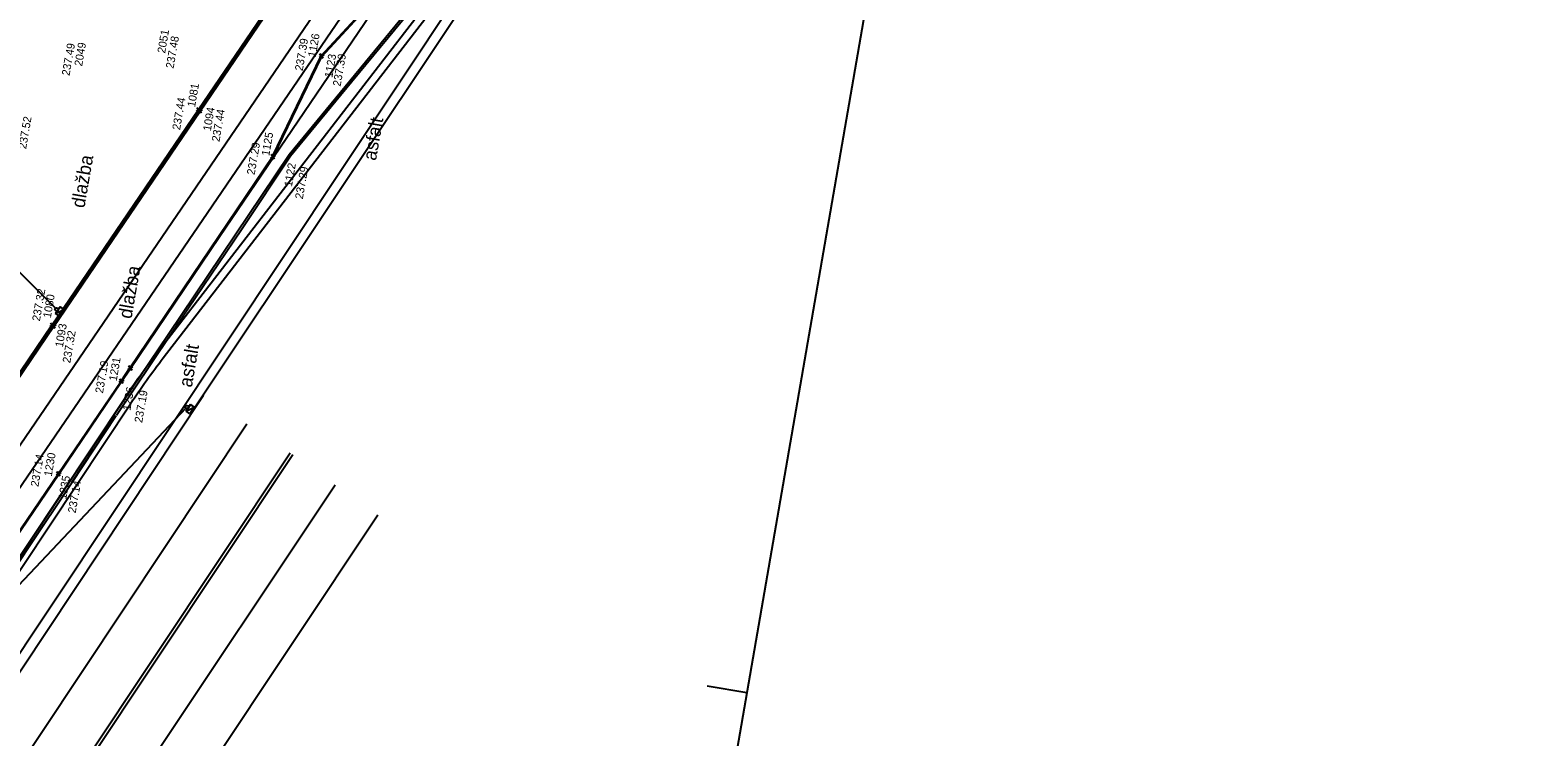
# Model space of a CAD drawing. Extents: x -264205 to -263659, y -1242401 to -1241986.
# Drawn here: x -263790.1 to -263696.7, y -1242294.8 to -1242250.6 of the extents above; entities that cross this region are included whole.
import ezdxf

# ---------------------------------------------------------------- set-up
doc = ezdxf.new("R2010")
doc.units = 0
for name, color, linetype in [('BOD_CISLO_2-4', 7, 'Continuous'), ('BOD_SYMBOL_2-4', 7, 'Continuous'), ('BOD_VYSKA_2-4', 7, 'Continuous'), ('POPIS_2-4', 7, 'Continuous'), ('PROJEKT_OBRUBNIKY_KOMUNIKACIE', 7, 'Continuous'), ('PROJEKT_TDZ_VODOROVNE', 7, 'Continuous'), ('RAM_NA_TLAC_2-4_1-250', 7, 'Continuous'), ('SITUACIA_DSP_2D', 7, 'Continuous'), ('SO_20-1_OBRUBNIKY_DOLNA_HRANA', 7, 'Continuous'), ('SO_20-1_OBRUBNIKY_HORNA_HRANA', 7, 'Continuous'), ('SO_20-4_OBRUBNIKY_HORNA_HRANA', 7, 'Continuous')]:
    doc.layers.add(name, color=color, linetype=linetype)

msp = doc.modelspace()

# ---------------------------------------------------------------- linework, layer by layer
at = {"layer": 'BOD_SYMBOL_2-4'}
for p, q in [((-263771.766, -1242252.117), (-263772.022, -1242252.297)), ((-263771.804, -1242252.335), (-263771.984, -1242252.079)), ((-263771.728, -1242252.142), (-263771.984, -1242252.322)), ((-263771.766, -1242252.36), (-263771.946, -1242252.104)), ((-263779.447, -1242255.487), (-263779.703, -1242255.667)), ((-263779.485, -1242255.705), (-263779.665, -1242255.449)), ((-263779.335, -1242255.573), (-263779.591, -1242255.753)), ((-263779.373, -1242255.791), (-263779.553, -1242255.535)), ((-263774.81, -1242258.413), (-263775.066, -1242258.593)), ((-263774.848, -1242258.631), (-263775.028, -1242258.375)), ((-263774.772, -1242258.438), (-263775.028, -1242258.618)), ((-263774.81, -1242258.656), (-263774.99, -1242258.4)), ((-263788.59, -1242268.95), (-263788.846, -1242269.13)), ((-263788.628, -1242269.168), (-263788.808, -1242268.912)), ((-263788.47, -1242269.032), (-263788.726, -1242269.212)), ((-263788.508, -1242269.25), (-263788.688, -1242268.994)), ((-263783.716, -1242271.634), (-263783.972, -1242271.814)), ((-263783.754, -1242271.852), (-263783.934, -1242271.596)), ((-263783.678, -1242271.659), (-263783.934, -1242271.839)), ((-263783.716, -1242271.877), (-263783.896, -1242271.621)), ((-263784.275, -1242272.461), (-263784.531, -1242272.641)), ((-263784.313, -1242272.679), (-263784.493, -1242272.423)), ((-263784.236, -1242272.485), (-263784.492, -1242272.665)), ((-263784.274, -1242272.703), (-263784.454, -1242272.447)), ((-263788.207, -1242278.251), (-263788.463, -1242278.431)), ((-263788.245, -1242278.469), (-263788.425, -1242278.213)), ((-263788.163, -1242278.267), (-263788.419, -1242278.447)), ((-263788.201, -1242278.485), (-263788.381, -1242278.229))]:
    msp.add_line(p, q, dxfattribs=at)
at = {"layer": 'PROJEKT_OBRUBNIKY_KOMUNIKACIE'}
for p, q in [((-263794.898, -1242288.032), (-263742.736, -1242211.145)), ((-263798.899, -1242284.125), (-263751.864, -1242215.081)), ((-263752.521, -1242232.37), (-263782.166, -1242270.821)), ((-263795.416, -1242290.541), (-263784.213, -1242273.68))]:
    msp.add_line(p, q, dxfattribs=at)
msp.add_arc((-263742.568, -1242301.35), 50, 142.36875, 146.39918, dxfattribs=at)
at = {"layer": 'PROJEKT_TDZ_VODOROVNE'}
for p, q in [((-263752.125, -1242232.675), (-263781.759, -1242271.113)), ((-263779.852, -1242274.272), (-263752.125, -1242232.675)), ((-263796.435, -1242299.302), (-263779.243, -1242273.429)), ((-263795, -1242290.817), (-263783.807, -1242273.971)), ((-263789.385, -1242294.564), (-263776.537, -1242275.228)), ((-263786.678, -1242296.363), (-263773.83, -1242277.027)), ((-263786.512, -1242296.474), (-263773.663, -1242277.138)), ((-263818.504, -1242350.278), (-263771.023, -1242279.037)), ((-263781.086, -1242300.054), (-263768.345, -1242280.91)), ((-263824.083, -1242346.553), (-263789.385, -1242294.564))]:
    msp.add_line(p, q, dxfattribs=at)
for points in [[(-263831.211, -1242326.873), (-263816.19, -1242319.41), (-263814.291, -1242315.804), (-263813.06, -1242301.353), (-263812.968, -1242299.181), (-263802.618, -1242291.831), (-263801.478, -1242290.893), (-263800.257, -1242289.755), (-263799.049, -1242288.464), (-263798.027, -1242287.218), (-263749.798, -1242216.488), (-263742.736, -1242211.145)], [(-263830.6, -1242328.105), (-263815.26, -1242320.378), (-263813.062, -1242316.188), (-263811.682, -1242301.389), (-263811.608, -1242300.055), (-263801.705, -1242293.023), (-263800.489, -1242292.021), (-263799.197, -1242290.817), (-263797.92, -1242289.454), (-263796.825, -1242288.118), (-263748.697, -1242217.536), (-263741.831, -1242212.341)]]:
    msp.add_lwpolyline(points, dxfattribs=at)
msp.add_arc((-263742.161, -1242301.641), 50, 142.36875, 146.39918, dxfattribs=at)
at = {"layer": 'RAM_NA_TLAC_2-4_1-250'}
msp.add_line((-263747.762, -1242291.607), (-263745.299, -1242292.033), dxfattribs=at)
msp.add_lwpolyline([(-263827.42, -1242331.09), (-263769.814, -1241998.542), (-263696.654, -1242011.215), (-263754.26, -1242343.763)], close=True, dxfattribs=at)
at = {"layer": 'SITUACIA_DSP_2D'}
for p, q in [((-263822.88, -1242337.914), (-263734.49, -1242204.937)), ((-263794.898, -1242288.032), (-263742.736, -1242211.145)), ((-263798.899, -1242284.125), (-263751.864, -1242215.081)), ((-263752.521, -1242232.37), (-263782.166, -1242270.821)), ((-263788.502, -1242267.989), (-263791.063, -1242265.427)), ((-263788.491, -1242268.322), (-263788.207, -1242267.91)), ((-263788.207, -1242267.91), (-263788.491, -1242268.322)), ((-263788.491, -1242268.322), (-263787.968, -1242268.075)), ((-263788.491, -1242268.322), (-263787.968, -1242268.075)), ((-263788.252, -1242268.487), (-263788.491, -1242268.322)), ((-263787.968, -1242268.075), (-263788.252, -1242268.487)), ((-263788.207, -1242267.91), (-263787.968, -1242268.075)), ((-263787.968, -1242268.075), (-263788.207, -1242267.91)), ((-263795.416, -1242290.541), (-263784.214, -1242273.68)), ((-263780.34, -1242274.426), (-263780.062, -1242274.011)), ((-263780.062, -1242274.011), (-263780.34, -1242274.426)), ((-263780.062, -1242274.011), (-263779.821, -1242274.173)), ((-263779.821, -1242274.173), (-263780.062, -1242274.011)), ((-263780.353, -1242274.236), (-263808.248, -1242303.783)), ((-263780.34, -1242274.426), (-263779.821, -1242274.173)), ((-263780.34, -1242274.426), (-263779.821, -1242274.173)), ((-263780.099, -1242274.588), (-263780.34, -1242274.426)), ((-263779.821, -1242274.173), (-263780.099, -1242274.588))]:
    msp.add_line(p, q, dxfattribs=at)
for centre in [(-263788.431, -1242268.059), (-263780.284, -1242274.163)]:
    msp.add_circle(centre, 0.1, dxfattribs=at)
msp.add_arc((-263742.568, -1242301.35), 50, 142.36875, 146.39918, dxfattribs=at)
at = {"layer": 'SO_20-1_OBRUBNIKY_DOLNA_HRANA'}
for points in [[(-263753.129, -1242233.288), (-263758.555, -1242239.941), (-263762.992, -1242245.362), (-263766.809, -1242249.987), (-263769.992, -1242253.855), (-263773.801, -1242258.482), (-263776.883, -1242263.085), (-263780.236, -1242268.055), (-263784.695, -1242274.697)], [(-263798.013, -1242294.654), (-263796.303, -1242292.18), (-263795.189, -1242290.524), (-263793.538, -1242288.034), (-263790.216, -1242283.022), (-263787.462, -1242278.872), (-263784.7, -1242274.704)]]:
    msp.add_lwpolyline(points, dxfattribs=at)
at = {"layer": 'SO_20-1_OBRUBNIKY_HORNA_HRANA'}
for points in [[(-263784.822, -1242274.627), (-263781.463, -1242269.63), (-263778.122, -1242264.669), (-263773.885, -1242258.373), (-263770.104, -1242253.768), (-263766.29, -1242249.13), (-263762.466, -1242244.514), (-263758.662, -1242239.844), (-263753.256, -1242233.184)], [(-263798.132, -1242294.573), (-263796.423, -1242292.099), (-263795.31, -1242290.444), (-263793.659, -1242287.955), (-263790.34, -1242282.948), (-263787.584, -1242278.79), (-263784.82, -1242274.623)]]:
    msp.add_lwpolyline(points, dxfattribs=at)
at = {"layer": 'SO_20-4_OBRUBNIKY_HORNA_HRANA'}
for p, q in [((-263788.718, -1242269.04), (-263792.095, -1242274.01)), ((-263788.598, -1242269.122), (-263791.976, -1242274.091)), ((-263784.403, -1242272.551), (-263783.844, -1242271.724)), ((-263784.364, -1242272.575), (-263783.806, -1242271.749)), ((-263788.335, -1242278.341), (-263784.403, -1242272.551)), ((-263788.291, -1242278.357), (-263784.364, -1242272.575)), ((-263792.256, -1242284.11), (-263788.335, -1242278.341)), ((-263792.218, -1242284.136), (-263788.291, -1242278.357))]:
    msp.add_line(p, q, dxfattribs=at)
for points in [[(-263788.718, -1242269.04), (-263779.575, -1242255.577), (-263771.592, -1242243.806), (-263758.354, -1242224.285), (-263758.272, -1242224.164), (-263750.296, -1242212.404)], [(-263788.598, -1242269.122), (-263779.463, -1242255.663), (-263771.455, -1242243.86), (-263758.151, -1242224.245), (-263750.15, -1242212.447)], [(-263771.894, -1242252.207), (-263767.033, -1242246.951), (-263753.675, -1242227.268), (-263747.417, -1242218.057)], [(-263771.856, -1242252.232), (-263766.995, -1242246.976), (-263753.637, -1242227.293), (-263747.379, -1242218.082)], [(-263783.844, -1242271.724), (-263774.938, -1242258.503), (-263771.894, -1242252.207)], [(-263783.806, -1242271.749), (-263774.9, -1242258.528), (-263771.856, -1242252.232)]]:
    msp.add_lwpolyline(points, dxfattribs=at)

# ---------------------------------------------------------------- texts
at = {"layer": 'BOD_CISLO_2-4'}
for s, p in [('2051', (-263781.649, -1242252.066)), ('2049', (-263786.836, -1242252.874)), ('1126', (-263772.236, -1242252.314)), ('1123', (-263771.2, -1242253.594)), ('1081', (-263779.777, -1242255.431)), ('1094', (-263778.792, -1242256.926)), ('1125', (-263775.139, -1242258.487)), ('1122', (-263773.725, -1242260.415)), ('1080', (-263788.79, -1242268.624)), ('1093', (-263788.037, -1242270.458)), ('1231', (-263784.675, -1242272.567)), ('1236', (-263783.822, -1242274.418)), ('1230', (-263788.734, -1242278.536)), ('1235', (-263787.831, -1242279.969))]:
    msp.add_text(s, height=0.5, rotation=80.1724, dxfattribs=at).set_placement(p)
at = {"layer": 'BOD_VYSKA_2-4'}
for s, p in [('237.49', (-263787.622, -1242253.47)), ('237.48', (-263781.122, -1242253.022)), ('237.39', (-263773.051, -1242253.17)), ('237.39', (-263770.683, -1242254.135)), ('237.44', (-263780.716, -1242256.866)), ('237.52', (-263790.336, -1242258.051)), ('237.44', (-263778.252, -1242257.6)), ('237.29', (-263776.057, -1242259.676)), ('237.29', (-263773.044, -1242261.188)), ('237.32', (-263789.476, -1242268.827)), ('237.32', (-263787.578, -1242271.445)), ('237.19', (-263785.533, -1242273.337)), ('237.19', (-263783.081, -1242275.179)), ('237.14', (-263789.569, -1242279.18)), ('237.14', (-263787.24, -1242280.828))]:
    msp.add_text(s, height=0.5, rotation=80.1724, dxfattribs=at).set_placement(p)
at = {"layer": 'POPIS_2-4'}
for s, p in [('asfalt', (-263768.469, -1242258.788)), ('dlažba', (-263786.693, -1242261.755)), ('dlažba', (-263783.75, -1242268.682)), ('asfalt', (-263779.982, -1242272.976))]:
    msp.add_text(s, height=0.8437, rotation=80.17241, dxfattribs=at).set_placement(p)

doc.saveas('drawing.dxf')
